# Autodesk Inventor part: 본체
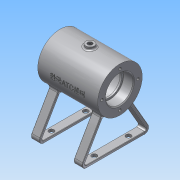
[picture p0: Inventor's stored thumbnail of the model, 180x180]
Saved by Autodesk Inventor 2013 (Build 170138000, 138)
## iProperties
Created: 2016-03
Part Number: 본체
Material: 알루미늄 6061
Document SubType Name: Modeling
Designer: Administrator
Mass: 212.897 g
Surface Area: 334.407 cm^2
Volume: 78.5599 cm^3
Density: 2.71 g/cm^3
Author: Administrator
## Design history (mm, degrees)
sketch "스케치1"
  geometry: L1 (-35, 0)-(35, 0); L2 (-35, 0)-(-35, 26); L3 (-35, 26)-(35, 26); L4 (35, 26)-(35, 0); 2 further points
  constraints: 8 end point, 2 perpendicular, 1 coincident, 1 horizontal, 1 midpoint, 1 parallel
  dimensions: "d0" = 70 distance of L1.start L1.end; "d2" = 52 diameter of L3 L1
revolve "회전1" sketch "스케치1" stored, may be unused: angle "d3" = 90 deg
node "작업 평면1"
sketch "스케치2"
  geometry: L1 (-16.613, -20)-(-38.264, -57.5); L2 (-33.934, -65)-(33.934, -65); L3 (38.264, -57.5)-(16.613, -20); L4 (0, 0)-(0, -84.745); L5 (14.183, -21.791)-(35.666, -59); L6 (33.934, -62)-(-33.934, -62); L7 (-35.666, -59)-(-14.183, -21.791); A1 r 26 centre (0, 0) between (-16.613, -20) and (16.613, -20) reference; A2 r 5 centre (-33.934, -60) between (-38.264, -57.5) and (-33.934, -65); A3 r 5 centre (33.934, -60) between (33.934, -65) and (38.264, -57.5); A4 r 2 centre (33.934, -60) between (33.934, -62) and (35.666, -59); A5 r 2 centre (-33.934, -60) between (-35.666, -59) and (-33.934, -62); 2 further points
  constraints: 14 end point, 12 point on circle, 4 centre point, 4 tangent, 2 parallel, 1 equal length, 1 equal radius, 1 horizontal, 1 midpoint, 1 perpendicular, 1 vertical alignment, 2 other
  dimensions: "d5" = 30 deg angle of L3 L4; "d6" = 65 distance from line of L2 point (0, 0); "d7" = 45 distance from line of L2 L3.end; "d8" = 5 radius of A2; "d10" = 3 distance between parallel lines of L6 L2; "d11" = 3 distance between parallel lines of L3 L5; "d12" = 3 distance between parallel lines of L1 L7
extrude "돌출1" join sketch "스케치2" distance "d13" = 10; taper "d14" = 0 deg
node "작업 평면2"
node "작업 평면3"
sketch "스케치3"
  geometry: C1 r 5 at (0, 0); 1 further point
  constraints: 1 centre point, 1 coincident
  dimensions: "d16" = 10 diameter of C1
extrude "돌출2" join sketch "스케치3" distance "d17" = 5; taper "d18" = 0 deg
sketch "스케치4"
  geometry: L1 (0, 0)-(7.506, -28.012); L2 (0, 0)-(0, -208.113); L3 (13.301, -26.459)-(5.796, 1.553); L4 (7.506, -28.012)-(13.301, -26.459); L5 (-31.268, -8.378)-(15.371, 4.119); L6 (-27.731, 0)-(31.59, 0); L7 (0, 0)-(5.796, 1.553)
  constraints: 14 end point, 3 point on line, 2 parallel, 1 collinear, 1 perpendicular, 1 vertical
  dimensions: "d24" = 15 deg angle of L6 L5; "d25" = 29 distance between parallel lines of L4 L5; "d28" = 12 diameter of L3 L1; "d29" = 15 deg angle of L1 L2
revolve "회전2" sketch "스케치4" stored, may be unused: angle "d30" = 90 deg
sketch "스케치5"
  geometry: L1 (-45, 53.934)-(5, 53.934); L2 (5, 53.934)-(5, 13.934); L3 (5, 13.934)-(-45, 13.934); L4 (-45, 13.934)-(-45, 53.934); L5 (10, 0)-(10, 67.868) reference; L6 (-50, 0)-(-50, 67.868) reference; 6 further points
  constraints: 8 end point, 4 coincident, 2 parallel, 1 horizontal, 1 horizontal alignment, 1 midpoint, 1 perpendicular
  dimensions: "d31" = 5 distance between parallel lines of L5 L2; "d32" = 5 distance between parallel lines of L6 L4; "d33" = 20 distance from line of point (-20, 33.934) L1
hole "구멍1" sketch "스케치5" at (-45, 53.934), (5, 53.934), (5, 13.934), (-45, 13.934) diameter "d34" = 6; stored, may be unused: countersink angle "d38" = 90 deg, drill point angle "d40" = 118 deg; dims "d35" = 6, "d36" = 4, "d37" = 2, "d39" = 8
hole "구멍2" diameter "d43" = 28; stored, may be unused: countersink angle "d47" = 90 deg, drill point angle "d49" = 0 deg; dims "d41" = 10, "d42" = 10, "d44" = 6, "d45" = 32, "d46" = 12, "d48" = 14
hole "구멍3" diameter "d52" = 28; stored, may be unused: countersink angle "d56" = 90 deg, drill point angle "d58" = 0 deg; dims "d50" = 10, "d51" = 10, "d53" = 6, "d54" = 32, "d55" = 12, "d57" = 14
sketch "스케치6"
  geometry: 2 further points
  constraints: 1 coincident
hole "구멍4" sketch "스케치6" at (0, 0) diameter "d59" = 42; stored, may be unused: countersink angle "d63" = 90 deg, drill point angle "d65" = 0 deg; dims "d60" = 6, "d61" = 32, "d62" = 12, "d64" = 42
hole "구멍7" diameter "d86" = 5.188; stored, may be unused: countersink angle "d90" = 90 deg, drill point angle "d92" = 0 deg; dims "d84" = 10, "d85" = 10, "d87" = 6, "d88" = 32, "d89" = 12, "d91" = 20
hole "구멍8" diameter "d95" = 5.188; stored, may be unused: countersink angle "d99" = 90 deg, drill point angle "d101" = 0 deg; dims "d93" = 10, "d94" = 10, "d96" = 6, "d97" = 32, "d98" = 12, "d100" = 20
sketch "스케치7"
  geometry: 2 further points
  constraints: 1 horizontal alignment
  dimensions: "d102" = 21 distance of point (21, 0) point (0, 0)
hole "구멍9" sketch "스케치7" at (21, 0) diameter "d103" = 3.242; stored, may be unused: countersink angle "d107" = 90 deg, drill point angle "d109" = 118 deg; dims "d104" = 8, "d105" = 32, "d106" = 12, "d108" = 10
node "작업 평면4"
sketch "스케치8"
  geometry: 2 further points
  constraints: 1 coincident, 1 other
feature "엠보싱1" sketch "스케치8" dims "d5" = 30 deg, "d6" = 65, "d7" = 45, "d8" = 5, "d10" = 3, "d11" = 3, "d12" = 3, "d113" = 0.5, "d114" = 0
chamfer "모따기1" distance "d115" = 1; stored, may be unused: second distance "d116" = 2, angle "d117" = 45 deg
fillet "모깎기1" dims "d118" = 0.3, "d119" = 3
fillet "모깎기2" dims "d120" = 2
fillet "모깎기3" dims "d121" = 0.5
fillet "모깎기4" dims "d122" = 3
node "솔리드1"
mirror "대칭1"
pattern_circular "원형 패턴1" dims angle "d111" = 360 deg
mirror "대칭2"
other parameters: "d15" = 29
